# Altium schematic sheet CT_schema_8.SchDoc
size 274 x 160 mm
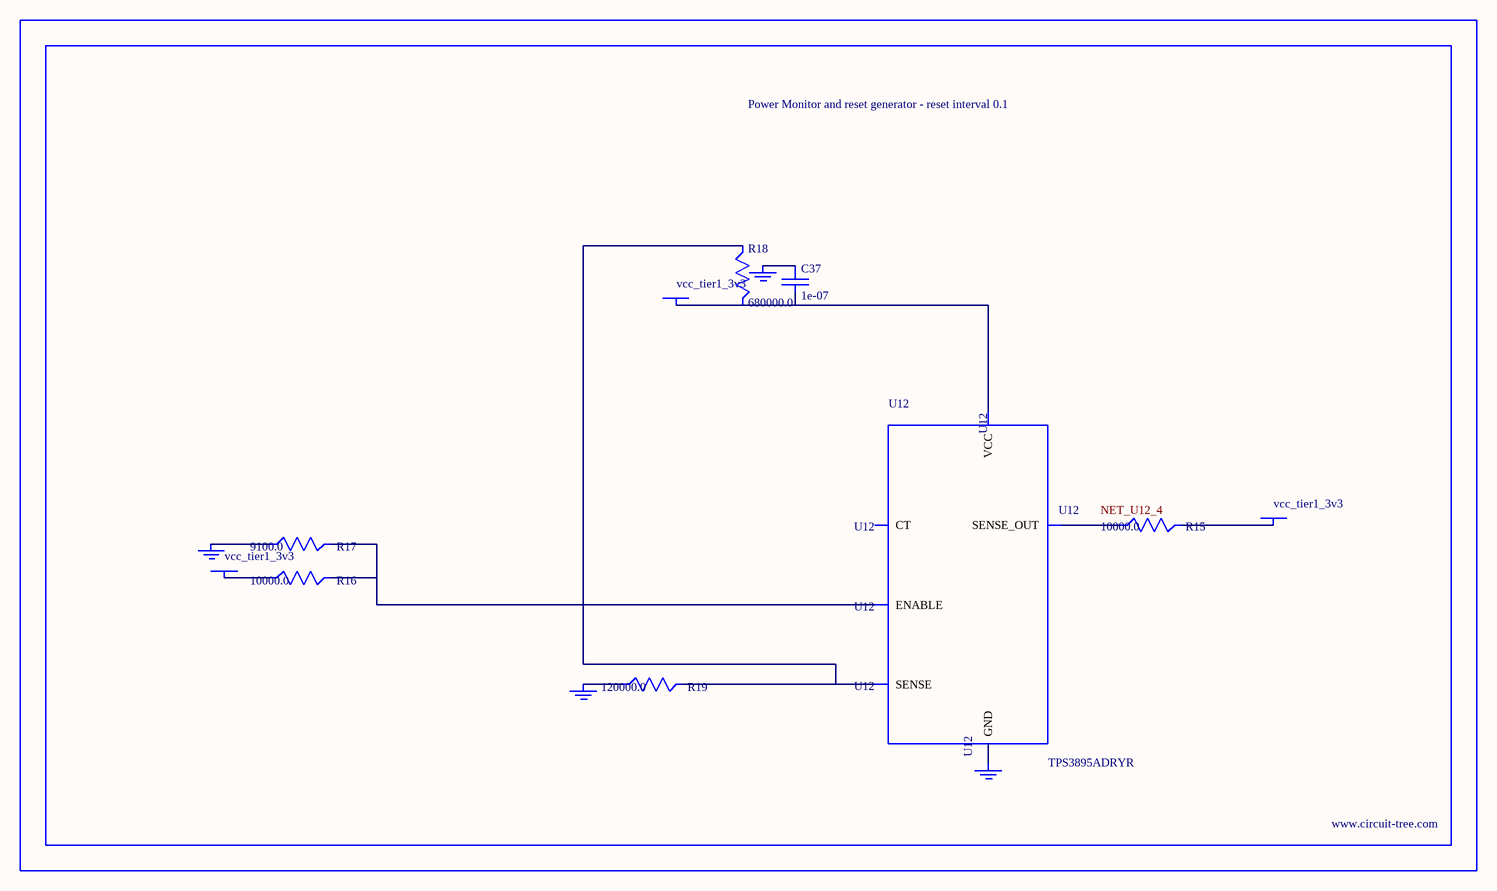
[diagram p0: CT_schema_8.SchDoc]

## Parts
BORDER7  (no value)
C37  1e-07  [C0402]
GND_INSTANCE_7_0  (no value)
GND_INSTANCE_7_1  (no value)
GND_INSTANCE_7_2  (no value)
GND_INSTANCE_7_3  (no value)
POWER_INSTANCE_7_0  vcc_tier1_3v3
POWER_INSTANCE_7_1  vcc_tier1_3v3
POWER_INSTANCE_7_2  vcc_tier1_3v3
R15  10000.0  [R0603]
R16  10000.0  [R0603]
R17  9100.0  [R0603]
R18  680000.0  [R0603]
R19  120000.0  [R0603]
U12  TPS3895ADRYR  [SON-6]

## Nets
NetC37_1: C37.1 GND_INSTANCE_7_2.0(GND)
NetC37_2: C37.2 POWER_INSTANCE_7_2.0(PWR) R18.2 U12.6(VCC)
NetGND_INSTANCE_7_0_0: GND_INSTANCE_7_0.0(GND) R17.1
NetGND_INSTANCE_7_1_0: GND_INSTANCE_7_1.0(GND) R19.1
NetGND_INSTANCE_7_3_0: GND_INSTANCE_7_3.0(GND) U12.2(GND)
NetPOWER_INSTANCE_7_0_0: POWER_INSTANCE_7_0.0(PWR) R16.1
NetPOWER_INSTANCE_7_1_0: POWER_INSTANCE_7_1.0(PWR) R15.2
NetR15_1: R15.1 U12.4(SENSE_OUT)
NetR16_2: R16.2 R17.2 U12.1(ENABLE)
NetR18_1: R18.1 R19.2 U12.3(SENSE)

Not connected (* = marked no-connect by the designer): U12 5(CT)

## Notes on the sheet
- Labels drawn without touching a wire or pin: NET_U12_4

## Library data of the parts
BORDER7 = BORDER_PAGE7
C37 = C0402C104K3RACTU
GND_INSTANCE_7_0-GND_INSTANCE_7_3 = GND
POWER_INSTANCE_7_0-POWER_INSTANCE_7_2 = PWR
R15 R16 = RC0603JR-0710KL
R17 = RC0603JR-079K1L
R18 = RC0603JR-07680KL
R19 = RC0603JR-07120KL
